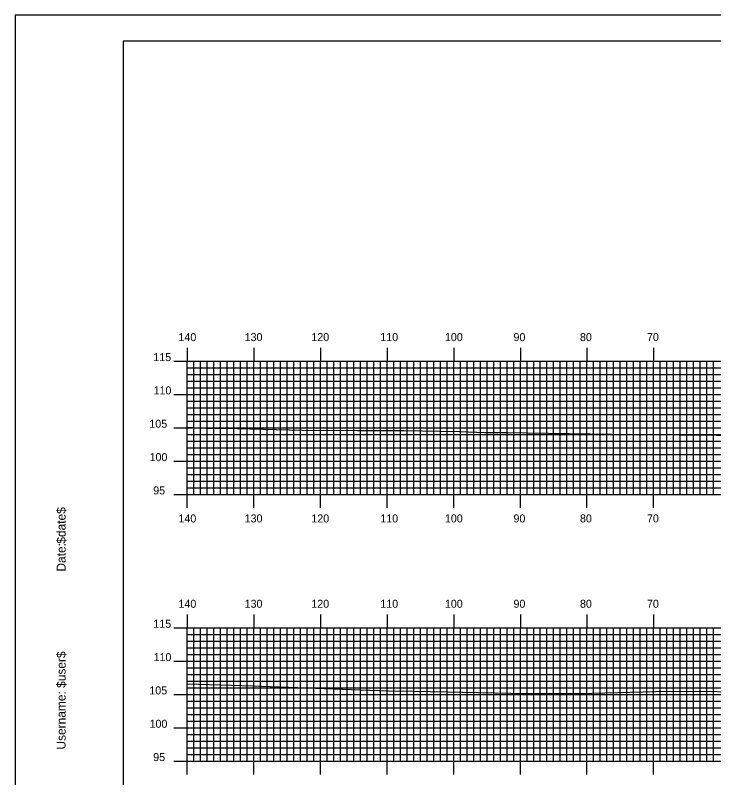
# Model space of a CAD drawing. Extents: x 1773596 to 1773940, y 442591 to 442811.
# Drawn here: x 1773596.4 to 1773701.2, y 442696.2 to 442810.5 of the extents above; entities that cross this region are included whole.
import ezdxf

# ---------------------------------------------------------------- set-up
doc = ezdxf.new("R2010")
doc.units = 0
for name, color, linetype in [('BORDER', 7, 'Continuous'), ('H_V ANNOTATION', 7, 'Continuous'), ('MAJOR', 7, 'Continuous'), ('MINOR', 7, 'Continuous'), ('PLOT BOUNDARY', 7, 'Continuous'), ('S_Roadway_Centerline', 7, 'Continuous')]:
    doc.layers.add(name, color=color, linetype=linetype)

msp = doc.modelspace()

# ---------------------------------------------------------------- linework, layer by layer
at = {"layer": 'BORDER'}
msp.add_lwpolyline([(1773612.55, 442596.67), (1773932.55, 442596.67), (1773932.55, 442806.67), (1773612.55, 442806.67)], close=True, dxfattribs=at)
at = {"layer": 'MAJOR'}
for p, q in [((1773622.15, 442760.67), (1773622.15, 442758.67)), ((1773632.15, 442760.67), (1773632.15, 442758.67)), ((1773642.15, 442760.67), (1773642.15, 442758.67)), ((1773652.15, 442760.67), (1773652.15, 442758.67)), ((1773662.15, 442760.67), (1773662.15, 442758.67)), ((1773672.15, 442760.67), (1773672.15, 442758.67)), ((1773682.15, 442760.67), (1773682.15, 442758.67)), ((1773692.15, 442760.67), (1773692.15, 442758.67)), ((1773620.14, 442758.67), (1773622.15, 442758.67)), ((1773622.15, 442758.67), (1773902.15, 442758.67)), ((1773622.15, 442738.67), (1773622.15, 442758.67)), ((1773622.15, 442738.67), (1773622.15, 442758.67)), ((1773622.15, 442758.67), (1773902.15, 442758.67)), ((1773632.15, 442738.67), (1773632.15, 442758.67)), ((1773642.15, 442738.67), (1773642.15, 442758.67)), ((1773652.15, 442738.67), (1773652.15, 442758.67)), ((1773662.15, 442738.67), (1773662.15, 442758.67)), ((1773672.15, 442738.67), (1773672.15, 442758.67)), ((1773682.15, 442738.67), (1773682.15, 442758.67)), ((1773692.15, 442738.67), (1773692.15, 442758.67)), ((1773620.14, 442753.67), (1773622.15, 442753.67)), ((1773622.15, 442753.67), (1773902.15, 442753.67)), ((1773620.14, 442748.67), (1773622.15, 442748.67)), ((1773622.15, 442748.67), (1773902.15, 442748.67)), ((1773620.14, 442743.67), (1773622.15, 442743.67)), ((1773622.15, 442743.67), (1773902.15, 442743.67)), ((1773620.14, 442738.67), (1773622.15, 442738.67)), ((1773622.15, 442738.67), (1773902.15, 442738.67)), ((1773622.15, 442738.67), (1773902.15, 442738.67)), ((1773622.15, 442736.66), (1773622.15, 442738.67)), ((1773632.15, 442736.66), (1773632.15, 442738.67)), ((1773642.15, 442736.66), (1773642.15, 442738.67)), ((1773652.15, 442736.66), (1773652.15, 442738.67)), ((1773662.15, 442736.66), (1773662.15, 442738.67)), ((1773672.15, 442736.66), (1773672.15, 442738.67)), ((1773682.15, 442736.66), (1773682.15, 442738.67)), ((1773692.15, 442736.66), (1773692.15, 442738.67)), ((1773622.15, 442720.67), (1773622.15, 442718.67)), ((1773632.15, 442720.67), (1773632.15, 442718.67)), ((1773642.15, 442720.67), (1773642.15, 442718.67)), ((1773652.15, 442720.67), (1773652.15, 442718.67)), ((1773662.15, 442720.67), (1773662.15, 442718.67)), ((1773672.15, 442720.67), (1773672.15, 442718.67)), ((1773682.15, 442720.67), (1773682.15, 442718.67)), ((1773692.15, 442720.67), (1773692.15, 442718.67)), ((1773620.14, 442718.67), (1773622.15, 442718.67)), ((1773622.15, 442718.67), (1773902.15, 442718.67)), ((1773622.15, 442698.67), (1773622.15, 442718.67)), ((1773622.15, 442698.67), (1773622.15, 442718.67)), ((1773622.15, 442718.67), (1773902.15, 442718.67)), ((1773632.15, 442698.67), (1773632.15, 442718.67)), ((1773642.15, 442698.67), (1773642.15, 442718.67)), ((1773652.15, 442698.67), (1773652.15, 442718.67)), ((1773662.15, 442698.67), (1773662.15, 442718.67)), ((1773672.15, 442698.67), (1773672.15, 442718.67)), ((1773682.15, 442698.67), (1773682.15, 442718.67)), ((1773692.15, 442698.67), (1773692.15, 442718.67)), ((1773620.14, 442713.67), (1773622.15, 442713.67)), ((1773622.15, 442713.67), (1773902.15, 442713.67)), ((1773620.14, 442708.67), (1773622.15, 442708.67)), ((1773622.15, 442708.67), (1773902.15, 442708.67)), ((1773620.14, 442703.67), (1773622.15, 442703.67)), ((1773622.15, 442703.67), (1773902.15, 442703.67)), ((1773620.14, 442698.67), (1773622.15, 442698.67)), ((1773622.15, 442698.67), (1773902.15, 442698.67)), ((1773622.15, 442698.67), (1773902.15, 442698.67)), ((1773622.15, 442696.66), (1773622.15, 442698.67)), ((1773632.15, 442696.66), (1773632.15, 442698.67)), ((1773642.15, 442696.66), (1773642.15, 442698.67)), ((1773652.15, 442696.66), (1773652.15, 442698.67)), ((1773662.15, 442696.66), (1773662.15, 442698.67)), ((1773672.15, 442696.66), (1773672.15, 442698.67)), ((1773682.15, 442696.66), (1773682.15, 442698.67)), ((1773692.15, 442696.66), (1773692.15, 442698.67))]:
    msp.add_line(p, q, dxfattribs=at)
at = {"layer": 'MINOR'}
for p, q in [((1773623.15, 442738.67), (1773623.15, 442758.67)), ((1773624.15, 442738.67), (1773624.15, 442758.67)), ((1773625.15, 442738.67), (1773625.15, 442758.67)), ((1773626.15, 442738.67), (1773626.15, 442758.67)), ((1773627.15, 442738.67), (1773627.15, 442758.67)), ((1773628.15, 442738.67), (1773628.15, 442758.67)), ((1773629.15, 442738.67), (1773629.15, 442758.67)), ((1773630.15, 442738.67), (1773630.15, 442758.67)), ((1773631.15, 442738.67), (1773631.15, 442758.67)), ((1773633.15, 442738.67), (1773633.15, 442758.67)), ((1773634.15, 442738.67), (1773634.15, 442758.67)), ((1773635.15, 442738.67), (1773635.15, 442758.67)), ((1773636.15, 442738.67), (1773636.15, 442758.67)), ((1773637.15, 442738.67), (1773637.15, 442758.67)), ((1773638.15, 442738.67), (1773638.15, 442758.67)), ((1773639.15, 442738.67), (1773639.15, 442758.67)), ((1773640.15, 442738.67), (1773640.15, 442758.67)), ((1773641.15, 442738.67), (1773641.15, 442758.67)), ((1773643.15, 442738.67), (1773643.15, 442758.67)), ((1773644.15, 442738.67), (1773644.15, 442758.67)), ((1773645.15, 442738.67), (1773645.15, 442758.67)), ((1773646.15, 442738.67), (1773646.15, 442758.67)), ((1773647.15, 442738.67), (1773647.15, 442758.67)), ((1773648.15, 442738.67), (1773648.15, 442758.67)), ((1773649.15, 442738.67), (1773649.15, 442758.67)), ((1773650.15, 442738.67), (1773650.15, 442758.67)), ((1773651.15, 442738.67), (1773651.15, 442758.67)), ((1773653.15, 442738.67), (1773653.15, 442758.67)), ((1773654.15, 442738.67), (1773654.15, 442758.67)), ((1773655.15, 442738.67), (1773655.15, 442758.67)), ((1773656.15, 442738.67), (1773656.15, 442758.67)), ((1773657.15, 442738.67), (1773657.15, 442758.67)), ((1773658.15, 442738.67), (1773658.15, 442758.67)), ((1773659.15, 442738.67), (1773659.15, 442758.67)), ((1773660.15, 442738.67), (1773660.15, 442758.67)), ((1773661.15, 442738.67), (1773661.15, 442758.67)), ((1773663.15, 442738.67), (1773663.15, 442758.67)), ((1773664.15, 442738.67), (1773664.15, 442758.67)), ((1773665.15, 442738.67), (1773665.15, 442758.67)), ((1773666.15, 442738.67), (1773666.15, 442758.67)), ((1773667.15, 442738.67), (1773667.15, 442758.67)), ((1773668.15, 442738.67), (1773668.15, 442758.67)), ((1773669.15, 442738.67), (1773669.15, 442758.67)), ((1773670.15, 442738.67), (1773670.15, 442758.67)), ((1773671.15, 442738.67), (1773671.15, 442758.67)), ((1773673.15, 442738.67), (1773673.15, 442758.67)), ((1773674.15, 442738.67), (1773674.15, 442758.67)), ((1773675.15, 442738.67), (1773675.15, 442758.67)), ((1773676.15, 442738.67), (1773676.15, 442758.67)), ((1773677.15, 442738.67), (1773677.15, 442758.67)), ((1773678.15, 442738.67), (1773678.15, 442758.67)), ((1773679.15, 442738.67), (1773679.15, 442758.67)), ((1773680.15, 442738.67), (1773680.15, 442758.67)), ((1773681.15, 442738.67), (1773681.15, 442758.67)), ((1773683.15, 442738.67), (1773683.15, 442758.67)), ((1773684.15, 442738.67), (1773684.15, 442758.67)), ((1773685.15, 442738.67), (1773685.15, 442758.67)), ((1773686.15, 442738.67), (1773686.15, 442758.67)), ((1773687.15, 442738.67), (1773687.15, 442758.67)), ((1773688.15, 442738.67), (1773688.15, 442758.67)), ((1773689.15, 442738.67), (1773689.15, 442758.67)), ((1773690.15, 442738.67), (1773690.15, 442758.67)), ((1773691.15, 442738.67), (1773691.15, 442758.67)), ((1773693.15, 442738.67), (1773693.15, 442758.67)), ((1773694.15, 442738.67), (1773694.15, 442758.67)), ((1773695.15, 442738.67), (1773695.15, 442758.67)), ((1773696.15, 442738.67), (1773696.15, 442758.67)), ((1773697.15, 442738.67), (1773697.15, 442758.67)), ((1773698.15, 442738.67), (1773698.15, 442758.67)), ((1773699.15, 442738.67), (1773699.15, 442758.67)), ((1773700.15, 442738.67), (1773700.15, 442758.67)), ((1773701.15, 442738.67), (1773701.15, 442758.67)), ((1773622.15, 442757.67), (1773902.15, 442757.67)), ((1773622.15, 442757.67), (1773624.15, 442757.67)), ((1773622.15, 442756.67), (1773902.15, 442756.67)), ((1773622.15, 442756.67), (1773624.15, 442756.67)), ((1773622.15, 442755.67), (1773902.15, 442755.67)), ((1773622.15, 442755.67), (1773624.15, 442755.67)), ((1773622.15, 442754.67), (1773902.15, 442754.67)), ((1773622.15, 442754.67), (1773624.15, 442754.67)), ((1773622.15, 442752.67), (1773902.15, 442752.67)), ((1773622.15, 442752.67), (1773624.15, 442752.67)), ((1773622.15, 442751.67), (1773902.15, 442751.67)), ((1773622.15, 442751.67), (1773624.15, 442751.67)), ((1773622.15, 442750.67), (1773902.15, 442750.67)), ((1773622.15, 442750.67), (1773624.15, 442750.67)), ((1773622.15, 442749.67), (1773902.15, 442749.67)), ((1773622.15, 442749.67), (1773624.15, 442749.67)), ((1773622.15, 442747.67), (1773902.15, 442747.67)), ((1773622.15, 442747.67), (1773624.15, 442747.67)), ((1773622.15, 442746.67), (1773902.15, 442746.67)), ((1773622.15, 442746.67), (1773624.15, 442746.67)), ((1773622.15, 442745.67), (1773902.15, 442745.67)), ((1773622.15, 442745.67), (1773624.15, 442745.67)), ((1773622.15, 442744.67), (1773902.15, 442744.67)), ((1773622.15, 442744.67), (1773624.15, 442744.67)), ((1773622.15, 442742.67), (1773902.15, 442742.67)), ((1773622.15, 442742.67), (1773624.15, 442742.67)), ((1773622.15, 442741.67), (1773902.15, 442741.67)), ((1773622.15, 442741.67), (1773624.15, 442741.67)), ((1773622.15, 442740.67), (1773902.15, 442740.67)), ((1773622.15, 442740.67), (1773624.15, 442740.67)), ((1773622.15, 442739.67), (1773902.15, 442739.67)), ((1773622.15, 442739.67), (1773624.15, 442739.67)), ((1773623.15, 442698.67), (1773623.15, 442718.67)), ((1773624.15, 442698.67), (1773624.15, 442718.67)), ((1773625.15, 442698.67), (1773625.15, 442718.67)), ((1773626.15, 442698.67), (1773626.15, 442718.67)), ((1773627.15, 442698.67), (1773627.15, 442718.67)), ((1773628.15, 442698.67), (1773628.15, 442718.67)), ((1773629.15, 442698.67), (1773629.15, 442718.67)), ((1773630.15, 442698.67), (1773630.15, 442718.67)), ((1773631.15, 442698.67), (1773631.15, 442718.67)), ((1773633.15, 442698.67), (1773633.15, 442718.67)), ((1773634.15, 442698.67), (1773634.15, 442718.67)), ((1773635.15, 442698.67), (1773635.15, 442718.67)), ((1773636.15, 442698.67), (1773636.15, 442718.67)), ((1773637.15, 442698.67), (1773637.15, 442718.67)), ((1773638.15, 442698.67), (1773638.15, 442718.67)), ((1773639.15, 442698.67), (1773639.15, 442718.67)), ((1773640.15, 442698.67), (1773640.15, 442718.67)), ((1773641.15, 442698.67), (1773641.15, 442718.67)), ((1773643.15, 442698.67), (1773643.15, 442718.67)), ((1773644.15, 442698.67), (1773644.15, 442718.67)), ((1773645.15, 442698.67), (1773645.15, 442718.67)), ((1773646.15, 442698.67), (1773646.15, 442718.67)), ((1773647.15, 442698.67), (1773647.15, 442718.67)), ((1773648.15, 442698.67), (1773648.15, 442718.67)), ((1773649.15, 442698.67), (1773649.15, 442718.67)), ((1773650.15, 442698.67), (1773650.15, 442718.67)), ((1773651.15, 442698.67), (1773651.15, 442718.67)), ((1773653.15, 442698.67), (1773653.15, 442718.67)), ((1773654.15, 442698.67), (1773654.15, 442718.67)), ((1773655.15, 442698.67), (1773655.15, 442718.67)), ((1773656.15, 442698.67), (1773656.15, 442718.67)), ((1773657.15, 442698.67), (1773657.15, 442718.67)), ((1773658.15, 442698.67), (1773658.15, 442718.67)), ((1773659.15, 442698.67), (1773659.15, 442718.67)), ((1773660.15, 442698.67), (1773660.15, 442718.67)), ((1773661.15, 442698.67), (1773661.15, 442718.67)), ((1773663.15, 442698.67), (1773663.15, 442718.67)), ((1773664.15, 442698.67), (1773664.15, 442718.67)), ((1773665.15, 442698.67), (1773665.15, 442718.67)), ((1773666.15, 442698.67), (1773666.15, 442718.67)), ((1773667.15, 442698.67), (1773667.15, 442718.67)), ((1773668.15, 442698.67), (1773668.15, 442718.67)), ((1773669.15, 442698.67), (1773669.15, 442718.67)), ((1773670.15, 442698.67), (1773670.15, 442718.67)), ((1773671.15, 442698.67), (1773671.15, 442718.67)), ((1773673.15, 442698.67), (1773673.15, 442718.67)), ((1773674.15, 442698.67), (1773674.15, 442718.67)), ((1773675.15, 442698.67), (1773675.15, 442718.67)), ((1773676.15, 442698.67), (1773676.15, 442718.67)), ((1773677.15, 442698.67), (1773677.15, 442718.67)), ((1773678.15, 442698.67), (1773678.15, 442718.67)), ((1773679.15, 442698.67), (1773679.15, 442718.67)), ((1773680.15, 442698.67), (1773680.15, 442718.67)), ((1773681.15, 442698.67), (1773681.15, 442718.67)), ((1773683.15, 442698.67), (1773683.15, 442718.67)), ((1773684.15, 442698.67), (1773684.15, 442718.67)), ((1773685.15, 442698.67), (1773685.15, 442718.67)), ((1773686.15, 442698.67), (1773686.15, 442718.67)), ((1773687.15, 442698.67), (1773687.15, 442718.67)), ((1773688.15, 442698.67), (1773688.15, 442718.67)), ((1773689.15, 442698.67), (1773689.15, 442718.67)), ((1773690.15, 442698.67), (1773690.15, 442718.67)), ((1773691.15, 442698.67), (1773691.15, 442718.67)), ((1773693.15, 442698.67), (1773693.15, 442718.67)), ((1773694.15, 442698.67), (1773694.15, 442718.67)), ((1773695.15, 442698.67), (1773695.15, 442718.67)), ((1773696.15, 442698.67), (1773696.15, 442718.67)), ((1773697.15, 442698.67), (1773697.15, 442718.67)), ((1773698.15, 442698.67), (1773698.15, 442718.67)), ((1773699.15, 442698.67), (1773699.15, 442718.67)), ((1773700.15, 442698.67), (1773700.15, 442718.67)), ((1773701.15, 442698.67), (1773701.15, 442718.67)), ((1773622.15, 442717.67), (1773902.15, 442717.67)), ((1773622.15, 442717.67), (1773624.15, 442717.67)), ((1773622.15, 442716.67), (1773902.15, 442716.67)), ((1773622.15, 442716.67), (1773624.15, 442716.67)), ((1773622.15, 442715.67), (1773902.15, 442715.67)), ((1773622.15, 442715.67), (1773624.15, 442715.67)), ((1773622.15, 442714.67), (1773902.15, 442714.67)), ((1773622.15, 442714.67), (1773624.15, 442714.67)), ((1773622.15, 442712.67), (1773902.15, 442712.67)), ((1773622.15, 442712.67), (1773624.15, 442712.67)), ((1773622.15, 442711.67), (1773902.15, 442711.67)), ((1773622.15, 442711.67), (1773624.15, 442711.67)), ((1773622.15, 442710.67), (1773902.15, 442710.67)), ((1773622.15, 442710.67), (1773624.15, 442710.67)), ((1773622.15, 442709.67), (1773902.15, 442709.67)), ((1773622.15, 442709.67), (1773624.15, 442709.67)), ((1773622.15, 442707.67), (1773902.15, 442707.67)), ((1773622.15, 442707.67), (1773624.15, 442707.67)), ((1773622.15, 442706.67), (1773902.15, 442706.67)), ((1773622.15, 442706.67), (1773624.15, 442706.67)), ((1773622.15, 442705.67), (1773902.15, 442705.67)), ((1773622.15, 442705.67), (1773624.15, 442705.67)), ((1773622.15, 442704.67), (1773902.15, 442704.67)), ((1773622.15, 442704.67), (1773624.15, 442704.67)), ((1773622.15, 442702.67), (1773902.15, 442702.67)), ((1773622.15, 442702.67), (1773624.15, 442702.67)), ((1773622.15, 442701.67), (1773902.15, 442701.67)), ((1773622.15, 442701.67), (1773624.15, 442701.67)), ((1773622.15, 442700.67), (1773902.15, 442700.67)), ((1773622.15, 442700.67), (1773624.15, 442700.67)), ((1773622.15, 442699.67), (1773902.15, 442699.67)), ((1773622.15, 442699.67), (1773624.15, 442699.67))]:
    msp.add_line(p, q, dxfattribs=at)
at = {"layer": 'PLOT BOUNDARY'}
msp.add_lwpolyline([(1773596.36, 442590.55), (1773936.36, 442590.55), (1773936.36, 442810.55), (1773596.36, 442810.55)], close=True, dxfattribs=at)
at = {"layer": 'S_Roadway_Centerline'}
for points in [[(1773622.15, 442748.74), (1773624.95, 442748.62), (1773629.72, 442748.57), (1773639.4, 442748.31), (1773647.7, 442748.28), (1773654.72, 442748.26), (1773663.02, 442748.1), (1773666.92, 442747.95), (1773670.09, 442747.95), (1773688.98, 442747.66), (1773690.45, 442747.64), (1773712.61, 442747.46)], [(1773622.15, 442710.26), (1773627.2, 442710.09), (1773631.97, 442709.96), (1773648.19, 442709.37), (1773652.36, 442709.23), (1773656.23, 442709.17), (1773670.7, 442708.86), (1773681, 442708.82), (1773692.48, 442709.09), (1773698.48, 442709.16), (1773704.92, 442709.08)]]:
    msp.add_lwpolyline(points, dxfattribs=at)

# ---------------------------------------------------------------- texts
at = {"layer": 'BORDER'}
for s, p in [('$date$', (1773603.92, 442731.28)), ('Date:', (1773603.92, 442727.1)), ('$user$', (1773603.92, 442709.65)), ('Username:', (1773603.92, 442700.4))]:
    msp.add_text(s, height=1.339, rotation=90, dxfattribs=at).set_placement(p)
at = {"layer": 'H_V ANNOTATION'}
for s, p in [('140', (1773620.85, 442761.67)), ('130', (1773630.78, 442761.67)), ('120', (1773640.79, 442761.67)), ('110', (1773651.13, 442761.67)), ('100', (1773660.83, 442761.67)), ('90', (1773671.12, 442761.67)), ('80', (1773681.1, 442761.67)), ('70', (1773691.15, 442761.67)), ('115', (1773617.08, 442758.67)), ('110', (1773617.11, 442753.67)), ('105', (1773616.48, 442748.67)), ('100', (1773616.51, 442743.67)), ('95', (1773617.06, 442738.67)), ('140', (1773620.85, 442734.47)), ('130', (1773630.78, 442734.47)), ('120', (1773640.79, 442734.47)), ('110', (1773651.13, 442734.47)), ('100', (1773660.83, 442734.47)), ('90', (1773671.12, 442734.47)), ('80', (1773681.1, 442734.47)), ('70', (1773691.15, 442734.47)), ('140', (1773620.85, 442721.67)), ('130', (1773630.78, 442721.67)), ('120', (1773640.79, 442721.67)), ('110', (1773651.13, 442721.67)), ('100', (1773660.83, 442721.67)), ('90', (1773671.12, 442721.67)), ('80', (1773681.1, 442721.67)), ('70', (1773691.15, 442721.67)), ('115', (1773617.08, 442718.67)), ('110', (1773617.11, 442713.67)), ('105', (1773616.48, 442708.67)), ('100', (1773616.51, 442703.67)), ('95', (1773617.06, 442698.67))]:
    msp.add_text(s, height=1.2, dxfattribs=at).set_placement(p)
at = {"layer": 'MAJOR'}
for p in [(1773622.14, 442738.67), (1773622.14, 442698.67)]:
    msp.add_text('-', height=0.012, dxfattribs=at).set_placement(p)

doc.saveas('drawing.dxf')
